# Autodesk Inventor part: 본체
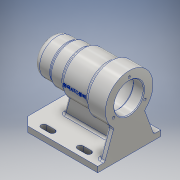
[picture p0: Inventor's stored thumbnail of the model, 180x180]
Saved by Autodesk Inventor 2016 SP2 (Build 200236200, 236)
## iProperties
Created: 2017-09
Part Number: 본체
Material: 알루미늄 6061
Document SubType Name: Modeling
Designer: Administrator
Density: 2.7 g/cm^3
Appearance: 알루미늄 - 평지
Mass: 693.606 g
Surface Area: 708.743 cm^2
Volume: 256.891 cm^3
Author: Administrator
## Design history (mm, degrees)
sketch "스케치1"
  geometry: L1 (-56, -45)-(56, -45); L2 (56, -45)-(56, 45); L3 (56, 45)-(-56, 45); L4 (-56, 45)-(-56, -45); L5 (-56, -45)-(56, 45); L6 (56, -45)-(-56, 45); 1 further point
  constraints: 12 end point, 2 midpoint, 2 parallel, 1 horizontal, 1 perpendicular
  dimensions: "d0" = 112 distance of L2.end L3.end; "d1" = 90 distance of L1.end L2.end
extrude "돌출1" new body sketch "스케치1" distance "d2" = 8; taper "d3" = 0 deg
chamfer "모따기1" distance "d4" = 12; stored, may be unused: second distance "d5" = 2, angle "d6" = 45 deg
sketch "스케치2"
  geometry: L1 (-56, 33)-(-44, 45) reference; L2 (-56, 33)-(-56, -33) reference; L3 (-44, -45)-(-56, -33) reference; L4 (-44, -45)-(56, -45) reference; L5 (56, -45)-(56, 45) reference; L6 (56, 45)-(-44, 45) reference; L7 (20, -38)-(32, -38); L8 (20, -30)-(32, -30); L9 (-20, -30)-(-32, -30); L10 (-32, -38)-(-20, -38); A1 r 4 centre (20, -34) between (20, -30) and (20, -38); A2 r 4 centre (32, -34) between (32, -38) and (32, -30); A3 r 4 centre (-20, -34) between (-20, -38) and (-20, -30); A4 r 4 centre (-32, -34) between (-32, -30) and (-32, -38); 1 further point
  constraints: 8 end point, 8 point on circle, 4 centre point, 4 horizontal, 4 tangent, 3 horizontal alignment
  dimensions: "d7" = 8 diameter of A1; "d8" = 8 diameter of A2; "d9" = 12 distance of A2.centre A1.centre; "d10" = 24 distance from line of A2.centre L5; "d11" = 34 vertical distance of A2.centre point (0, 0); "d12" = 8 diameter of A3; "d13" = 8 diameter of A4; "d14" = 12 distance of A4.centre A3.centre; "d15" = 40 distance of A3.centre A1.centre
extrude "돌출2" cut sketch "스케치2" stored distance "d16" = 8; taper "d17" = 0 deg
sketch "스케치3"
  geometry: L1 (-56, 70)-(56, 70); L2 (-56, 0)-(44, 0) reference; L3 (-56, 0)-(-56, 8) reference; L4 (-56, 70)-(-56, 104); L5 (-56, 104)-(-28, 104); L6 (-28, 104)-(-28, 100); L7 (-28, 100)-(11, 100); L8 (11, 100)-(11, 97); L9 (11, 97)-(31, 97); L10 (31, 97)-(31, 95); L11 (31, 95)-(56, 95); L12 (56, 95)-(56, 70); 2 further points
  constraints: 21 end point, 8 perpendicular, 1 horizontal, 1 midpoint, 1 point on line, 1 vertical
  dimensions: "d18" = 70 distance from line of L1 point (0, 0); "d19" = 68 diameter of L5 L1; "d20" = 60 diameter of L7 L1; "d21" = 54 diameter of L9 L1; "d22" = 50 diameter of L11 L1; "d23" = 25 distance from line of L10.end L12; "d24" = 45 distance between parallel lines of L8 L12; "d25" = 84 distance between parallel lines of L6 L12; "d26" = 112 distance between parallel lines of L12 L4
revolve "회전1" sketch "스케치3" stored, may be unused: angle "d27" = 90 deg
sketch "스케치4"
  geometry: L1 (0, 0)-(0, 90) reference; L2 (0, 90)-(-8, 90) reference; L3 (-8, 0)-(-8, 90) reference; L4 (0, 0)-(-8, 0) reference; L5 (-8, 80)-(-43.992, 66.9); L6 (-8, 10)-(-43.992, 23.1); A1 r 34 centre (-70, 45) between (-43.992, 66.9) and (-43.992, 23.1) reference; A2 r 34 centre (-70, 45) between (-43.992, 66.9) and (-43.992, 23.1) reference; 1 further point
  constraints: 4 end point, 4 point on circle, 2 point on line, 1 equal length
  dimensions: "d28" = 10 distance from line of L5.start L2; "d29" = 110 deg angle of L5 L3; "d30" = 110 deg angle of L6 L3
extrude "돌출3" join sketch "스케치4" distance "d31" = 8; taper "d32" = 0 deg
sketch "스케치5"
  geometry: L1 (31, 45)-(56, 45) reference; L2 (11, 43)-(31, 43) reference; L3 (31, 43)-(31, 97) reference; L4 (11, 40)-(11, 100) reference; L5 (-28, 40)-(11, 40) reference; L6 (-56, 8)-(44, 8) reference; L7 (56, 8)-(44, 8) reference; L8 (34, 8)-(24.622, 43); L9 (-28, 36)-(-28, 104) reference; L10 (-48, 36)-(-28, 36) reference; L11 (-48, 43.992)-(-48, 8) reference; 1 further point
  constraints: 2 end point, 2 point on line
  dimensions: "d33" = 22 distance of L8.start L7.start; "d34" = 105 deg angle of L8 L6
feature "리브1" sketch "스케치5" dims "d35" = 1, "d36" = 8, "d37" = 0, "d38" = 0, "d39" = 1, "d40" = 1
sketch "스케치6"
  geometry: L1 (0, 0)-(0, 90) reference; L2 (0, 90)-(-8, 90) reference; L3 (-8, 80)-(-8, 90) reference; L4 (-8, 80)-(-43.992, 66.9) reference; L5 (-43.992, 23.1)-(-8, 10) reference; L6 (-8, 0)-(-8, 10) reference; L7 (0, 0)-(-8, 0) reference; C1 r 21 at (-70, 45); A1 r 34 centre (-70, 45) between (-43.992, 66.9) and (-43.992, 23.1) reference; 1 further point
  constraints: 1 centre point, 1 coincident
  dimensions: "d41" = 42 diameter of C1
extrude "돌출4" cut sketch "스케치6" distance "d42" = 15; taper "d43" = 0 deg
sketch "스케치7"
  geometry: C1 r 21 at (0, 0) reference; C2 r 24 at (0, 0); 1 further point
  constraints: 1 centre point, 1 coincident
  dimensions: "d44" = 48 diameter of C2
extrude "돌출5" cut sketch "스케치7" distance "d45" = 54; taper "d46" = 0 deg
sketch "스케치8"
  geometry: C1 r 27 at (0, 0) reference; C2 r 21 at (0, 0); 1 further point
  constraints: 1 centre point, 1 coincident
  dimensions: "d47" = 42 diameter of C2
extrude "돌출6" cut sketch "스케치8" distance "d48" = 12; taper "d49" = 0 deg
sketch "스케치9"
  geometry: L1 (25, 49)-(25, 91) reference; L2 (25, 70)-(50, 70); L3 (25, 87.5)-(43, 87.5); L4 (43, 87.5)-(43, 86); L5 (43, 86)-(47, 86); L6 (47, 86)-(47, 80.5); L7 (47, 80.5)-(50, 80.5); L8 (50, 80.5)-(50, 70); 1 further point
  constraints: 15 end point, 5 perpendicular, 2 horizontal, 1 midpoint, 1 point on line
  dimensions: "d50" = 35 diameter of L3 L2; "d51" = 18 distance between parallel lines of L4 L1; "d52" = 32 diameter of L5 L2; "d53" = 4 distance of L4.end L5.end; "d54" = 21 diameter of L7 L2; "d55" = 3 distance of L6.end L7.end
revolve "회전2" sketch "스케치9" stored, may be unused: angle "d56" = 90 deg
sketch "스케치10"
  geometry: L1 (-70, 45)-(-96, 45); L2 (-70, 45)-(-57, 22.483); L3 (-70, 45)-(-57, 67.517); A1 r 34 centre (-70, 45) between (-43.992, 66.9) and (-43.992, 23.1) reference; A2 r 26 centre (-70, 45) between (-96, 45) and (-57, 22.483); 1 further point
  constraints: 6 end point, 3 point on circle, 1 centre point, 1 coincident, 1 horizontal, 1 horizontal alignment
  dimensions: "d57" = 52 diameter of A2; "d65" = 120 deg angle of L2 L1; "d66" = 120 deg angle of L3 L1
hole "구멍1" sketch "스케치10" at (-96, 45), (-57, 22.483), (-57, 67.517) diameter "d58" = 3.242; stored, may be unused: countersink angle "d62" = 90 deg, drill point angle "d64" = 118 deg; dims "d59" = 8, "d60" = 4, "d61" = 2, "d63" = 11
fillet "모깎기1" dims "d67" = 9
chamfer "모따기2" distance "d68" = 1; stored, may be unused: second distance "d69" = 2, angle "d70" = 45 deg
fillet "모깎기3" dims "d72" = 3
fillet "모깎기4" dims "d73" = 3
fillet "모깎기5" dims "d74" = 3
fillet "모깎기6" dims "d75" = 3
fillet "모깎기7" dims "d76" = 0.3
node "작업 평면1"
sketch "스케치12"
  geometry: L1 (-52.5, -70)-(47.5, -70) reference; L2 (47.5, 34)-(47.5, -26.008) reference; 2 further points
  constraints: 1 other
  dimensions: "d77" = 70 distance from line of point (-0.5, 0) L1; "d78" = 48 distance from line of point (-0.5, 0) L2
feature "엠보싱1" sketch "스케치12" dims "d0" = 112, "d1" = 90, "d7" = 8, "d8" = 8, "d9" = 12, "d10" = 24, "d11" = 34, "d12" = 8, "d13" = 8, "d14" = 12, "d15" = 40, "d79" = 0.5, "d80" = 0
fillet "모깎기8" dims "d81" = 3
fillet "모깎기9" dims "d82" = 3
fillet "모깎기10" dims "d83" = 3
fillet "모깎기11" dims "d84" = 3
fillet "모깎기12" dims "d85" = 3
node "솔리드1"
mirror "대칭1"
node "투영된 루프1"
node "투영된 루프2"
node "투영된 루프3"
node "투영된 루프4"
node "투영된 루프5"
